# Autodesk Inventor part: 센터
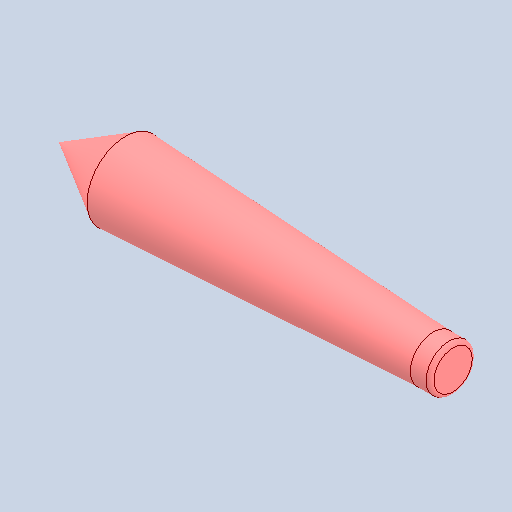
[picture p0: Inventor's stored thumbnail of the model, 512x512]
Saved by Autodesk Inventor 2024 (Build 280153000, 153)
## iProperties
Created: 2024-08
Part Number: 센터
Material: 강철, 합금
Document SubType Name: Modeling
Designer: user
Density: 7.73 g/cm^3
Appearance: 기본값
Author: jhkim
Sending System: Autodesk Inventor 2025
Preprocessor: ST-DEVELOPER v20
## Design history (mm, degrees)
feature "솔리드1"
node "솔리드2"
